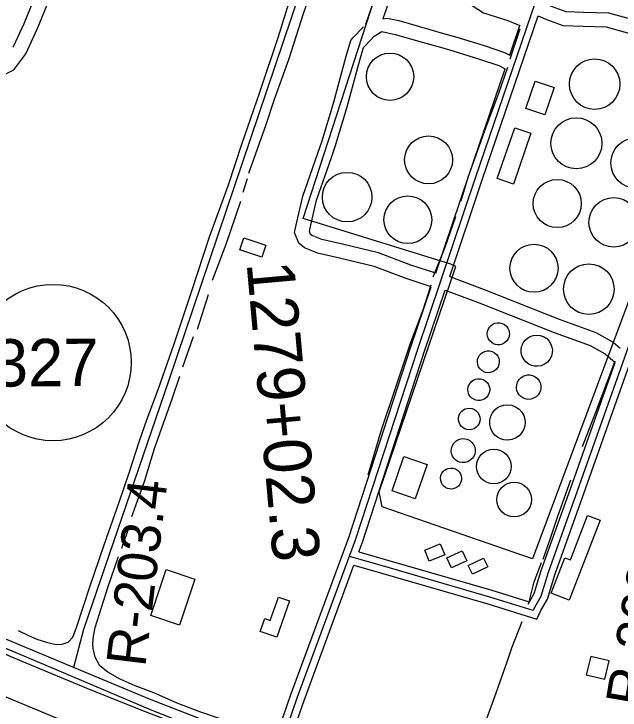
# Model space of a CAD drawing. Extents: x 3329332 to 3367211, y 631066 to 656469.
# Drawn here: x 3336928 to 3338207, y 649803 to 651272 of the extents above; entities that cross this region are included whole.
import ezdxf

# ---------------------------------------------------------------- set-up
doc = ezdxf.new("R2010")
doc.units = 0
for name, color, linetype in [('V-BLDG-OTLN', 7, 'Continuous'), ('V-DOMW-TANK', 7, 'Continuous'), ('V-LEVE-TOET', 7, 'Continuous'), ('V-RIVR-RANG-IDEN', 7, 'Continuous'), ('V-ROAD-CNTR', 7, 'Continuous'), ('V-ROAD-IDEN', 7, 'Continuous'), ('V-SITE-OTLN', 7, 'Continuous'), ('V-SURV-IDEN', 7, 'Continuous'), ('V-SURV-LINE', 7, 'Continuous'), ('V-TOPO-SHOR', 7, 'Continuous')]:
    doc.layers.add(name, color=color, linetype=linetype)

msp = doc.modelspace()

# ---------------------------------------------------------------- linework, layer by layer
at = {"layer": 'V-BLDG-OTLN'}
for points in [[(3338008.2600000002, 651072.2880000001), (3338027.802, 651129.833), (3338067.4960000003, 651116.351), (3338047.954, 651058.808)], [(3338018.4220000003, 651020.172), (3337981.5870000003, 650912.863), (3337947.645, 650924.514), (3337984.48, 651031.823)], [(3337413.113, 650799.818), (3337459.65, 650783.747), (3337450.913, 650758.446), (3337404.376, 650774.517)], [(3337799.433, 650321.372), (3337774.483, 650249.055), (3337725.877, 650265.824), (3337750.828, 650338.1410000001)], [(3338164.7060000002, 650203.573), (3338099.4760000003, 650035.297), (3338061.508, 650050.0160000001), (3338090.352, 650124.426), (3338101.8680000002, 650119.962), (3338138.252, 650213.828)], [(3337794.664, 650140.513), (3337827.538, 650154.157), (3337837.147, 650131.007), (3337804.273, 650117.363)], [(3337841.2, 650124.4450000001), (3337873.292, 650139.278), (3337883.18, 650117.885), (3337851.09, 650103.051)], [(3337886.551, 650107.985), (3337918.649, 650124.006), (3337927.759, 650105.757), (3337895.659, 650089.735)], [(3337216.929, 650002.581), (3337249.271, 650099.85), (3337309.724, 650079.7490000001), (3337277.382, 649982.479)], [(3337509.379, 650033.7390000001), (3337482.665, 649957.123), (3337447.741, 649969.301), (3337457.159, 649996.3200000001), (3337468.943, 649992.212), (3337486.237, 650041.808)], [(3338135.39169175, 649877.63821801), (3338174.2876139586, 649868.30823667), (3338183.618595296, 649907.2041588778), (3338144.7226730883, 649916.5351402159)]]:
    msp.add_lwpolyline(points, close=True, dxfattribs=at)
at = {"layer": 'V-DOMW-TANK'}
for points in [[(3337934.485, 650614.566), (3337938.015, 650617.161), (3337942.359, 650619.18), (3337947.381, 650620.313), (3337952.788, 650620.284), (3337958.161, 650618.965), (3337963.052, 650616.43), (3337967.091, 650612.946), (3337970.083, 650608.893), (3337972.012, 650604.654), (3337973.009, 650600.486), (3337973.218, 650595.97), (3337972.444, 650591.1140000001), (3337970.517, 650586.234), (3337967.4, 650581.745), (3337963.261, 650578.058), (3337958.438, 650575.486), (3337953.367, 650574.138), (3337948.454, 650573.938), (3337943.991, 650574.667), (3337939.969, 650576.1410000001), (3337935.984, 650578.552), (3337932.305, 650581.995), (3337929.315, 650586.41), (3337927.366, 650591.563), (3337926.68, 650597.054), (3337927.2800000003, 650602.43), (3337928.988, 650607.281), (3337931.501, 650611.361)], [(3338011.43, 650587.962), (3338016.74, 650591.145), (3338023.122, 650593.42), (3338030.339, 650594.354), (3338037.947, 650593.605), (3338045.343, 650591.041), (3338051.892, 650586.826), (3338057.1210000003, 650581.39), (3338060.7970000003, 650575.289), (3338062.958, 650569.0700000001), (3338063.816, 650563.071), (3338063.511, 650556.685), (3338061.786, 650549.9500000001), (3338058.432, 650543.334), (3338053.453, 650537.422), (3338047.139, 650532.779), (3338040.012, 650529.789), (3338032.696, 650528.56), (3338025.752, 650528.9230000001), (3338019.5670000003, 650530.537), (3338014.096, 650533.144), (3338008.802, 650537.059), (3338004.078, 650542.39), (3338000.447, 650549.001), (3337998.378, 650556.509), (3337998.136, 650564.333), (3337999.6890000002, 650571.818), (3338002.732, 650578.429), (3338006.806, 650583.8420000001)], [(3337913.359, 650555.1680000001), (3337916.849, 650557.759), (3337921.148, 650559.7880000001), (3337926.123, 650560.941), (3337931.488, 650560.943), (3337936.83, 650559.6630000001), (3337941.696, 650557.177), (3337945.724, 650553.74), (3337948.7120000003, 650549.737), (3337950.651, 650545.542), (3337951.665, 650541.411), (3337951.897, 650536.932), (3337951.157, 650532.109), (3337949.269, 650527.256), (3337946.205, 650522.783), (3337942.117, 650519.105), (3337937.346, 650516.524), (3337932.324, 650515.158), (3337927.448, 650514.931), (3337923.018, 650515.629), (3337919.0160000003, 650517.071), (3337915.0470000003, 650519.4400000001), (3337911.379, 650522.834), (3337908.389, 650527.2000000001), (3337906.4250000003, 650532.302), (3337905.7120000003, 650537.745), (3337906.2770000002, 650543.083), (3337907.947, 650547.91), (3337910.416, 650551.973)], [(3337894.053, 650496.99), (3337897.629, 650499.434), (3337901.989, 650501.287), (3337906.988, 650502.2390000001), (3337912.3310000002, 650502.032), (3337917.603, 650500.55), (3337922.348, 650497.881), (3337926.225, 650494.303), (3337929.0470000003, 650490.197), (3337930.815, 650485.943), (3337931.66, 650481.792), (3337931.716, 650477.321), (3337930.792, 650472.547), (3337928.724, 650467.79), (3337925.4960000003, 650463.454), (3337921.279, 650459.948), (3337916.427, 650457.566), (3337911.373, 650456.403), (3337906.507, 650456.368), (3337902.122, 650457.237), (3337898.196, 650458.83), (3337894.336, 650461.343), (3337890.815, 650464.867), (3337888.007, 650469.332), (3337886.25, 650474.4890000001), (3337885.754, 650479.939), (3337886.5270000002, 650485.231), (3337888.376, 650489.9720000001), (3337890.995, 650493.92)], [(3338006.4590000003, 650509.2930000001), (3338011.223, 650510.267), (3338016.54, 650510.29), (3338022.127, 650509.1020000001), (3338027.5640000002, 650506.5650000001), (3338032.3710000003, 650502.741), (3338036.123, 650497.916), (3338038.578, 650492.53), (3338039.715, 650487.055), (3338039.6920000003, 650481.886), (3338038.765, 650477.223), (3338036.876, 650472.574), (3338033.845, 650468.0380000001), (3338029.639, 650464.011), (3338024.414, 650460.931), (3338018.5300000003, 650459.137), (3338012.474, 650458.781), (3338006.738, 650459.774), (3338001.6920000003, 650461.855), (3337997.532, 650464.659), (3337994.161, 650468.011), (3337991.261, 650472.289), (3337989.15, 650477.4670000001), (3337988.183, 650483.306), (3337988.607, 650489.405), (3337990.465, 650495.26), (3337993.563, 650500.398), (3337997.538, 650504.498), (3338001.9620000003, 650507.4450000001)], [(3338006.376, 650410.108), (3338005.716, 650403.11), (3338003.508, 650395.747), (3337999.511, 650388.52), (3337993.7090000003, 650382.069), (3337986.393, 650377.035), (3337978.14, 650373.877), (3337969.6550000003, 650372.748), (3337961.606, 650373.488), (3337954.465, 650375.6950000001), (3337948.4050000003, 650378.946), (3337942.773, 650383.517), (3337937.772, 650389.62), (3337933.9790000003, 650397.136), (3337931.92, 650405.662), (3337931.92, 650414.554), (3337933.9790000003, 650423.08), (3337937.772, 650430.596), (3337942.773, 650436.701), (3337948.4050000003, 650441.27), (3337954.465, 650444.5210000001), (3337961.606, 650446.728), (3337969.6550000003, 650447.466), (3337978.14, 650446.339), (3337986.393, 650443.181), (3337993.7090000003, 650438.145), (3337999.511, 650431.696), (3338003.508, 650424.469), (3338005.716, 650417.106)], [(3337876.1040000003, 650436.4720000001), (3337879.909, 650438.4670000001), (3337884.415, 650439.792), (3337889.449, 650440.154), (3337894.69, 650439.335), (3337899.707, 650437.269), (3337904.078, 650434.0920000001), (3337907.484, 650430.123), (3337909.792, 650425.757), (3337911.039, 650421.362), (3337911.397, 650417.176), (3337910.937, 650412.7660000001), (3337909.478, 650408.169), (3337906.898, 650403.72), (3337903.216, 650399.823), (3337898.661, 650396.855), (3337893.609, 650395.0650000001), (3337888.4930000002, 650394.502), (3337883.698, 650395.024), (3337879.4790000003, 650396.388), (3337875.795, 650398.408), (3337872.2830000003, 650401.328), (3337869.221, 650405.203), (3337866.968, 650409.926), (3337865.829, 650415.205), (3337865.969, 650420.631), (3337867.339, 650425.755), (3337869.7060000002, 650430.211), (3337872.741, 650433.799)], [(3337869.002, 650375.063), (3337873.6920000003, 650375.919), (3337878.9080000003, 650375.833), (3337884.366, 650374.553), (3337889.648, 650371.952), (3337894.2800000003, 650368.101), (3337897.866, 650363.2930000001), (3337900.162, 650357.958), (3337901.166, 650352.5650000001), (3337901.039, 650347.4940000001), (3337900.031, 650342.938), (3337898.085, 650338.4180000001), (3337895.02, 650334.029), (3337890.809, 650330.164), (3337885.619, 650327.25), (3337879.811, 650325.612), (3337873.864, 650325.386), (3337868.256, 650326.48), (3337863.349, 650328.62), (3337859.325, 650331.459), (3337856.0870000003, 650334.819), (3337853.3310000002, 650339.0750000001), (3337851.366, 650344.1950000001), (3337850.539, 650349.944), (3337851.08, 650355.9180000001), (3337853.021, 650361.6240000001), (3337856.167, 650366.6), (3337860.15, 650370.545), (3337864.554, 650373.34)], [(3337836.611, 650309.31), (3337840.148, 650311.532), (3337844.418, 650313.16), (3337849.271, 650313.893), (3337854.414, 650313.498), (3337859.438, 650311.8740000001), (3337863.915, 650309.127), (3337867.519, 650305.533), (3337870.0870000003, 650301.476), (3337871.633, 650297.31), (3337872.299, 650293.28), (3337872.186, 650288.969), (3337871.119, 650284.4), (3337868.953, 650279.89), (3337865.682, 650275.831), (3337861.49, 650272.609), (3337856.7260000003, 650270.49), (3337851.811, 650269.556), (3337847.1210000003, 650269.699), (3337842.927, 650270.699), (3337839.199, 650272.378), (3337835.572, 650274.942), (3337832.31, 650278.469), (3337829.7660000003, 650282.876), (3337828.2630000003, 650287.912), (3337827.987, 650293.182), (3337828.9250000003, 650298.252), (3337830.884, 650302.754), (3337833.553, 650306.463)]]:
    msp.add_lwpolyline(points, close=True, dxfattribs=at)
for centre, radius in [((3337721.422526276, 651139.4142933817), 49.92223026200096), ((3338153.103905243, 651123.7239077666), 53.24630997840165), ((3338114.531359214, 650998.9432229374), 53.8207755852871), ((3337802.758725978, 650963.8763574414), 50.51238823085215), ((3338240.245628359, 650957.4500719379), 52.8947480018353), ((3337630.98572131, 650885.4010597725), 52.26802205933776), ((3338074.1135516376, 650871.9143010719), 50.777583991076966), ((3337759.032136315, 650837.666480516), 50.40586754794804), ((3338193.3709002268, 650832.2113166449), 52.236251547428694), ((3338025.1636538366, 650735.4327266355), 50.663710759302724), ((3338140.786429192, 650691.2992106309), 53.38208720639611), ((3337940.2538369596, 650317.2020386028), 36.55618293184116), ((3337983.3630298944, 650247.2283144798), 36.59716773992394)]:
    msp.add_circle(centre, radius, dxfattribs=at)
at = {"layer": 'V-LEVE-TOET'}
msp.add_lwpolyline([(3337615.179, 649642.509), (3337494.578, 649685.679), (3337361.847, 649739.015), (3337202.353, 649801.209), (3337090.813, 649845.022), (3336945.235, 649905.397), (3336818.775, 649959.046), (3336694.376, 650007.459), (3336566.857, 650058.327), (3336448.007, 650103.2270000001), (3336336.455, 650144.951), (3336224.214, 650188.074), (3336140.117, 650219.892), (3336101.211, 650237.47), (3336073.77, 650249.868), (3336031, 650261.253), (3335964.251, 650281.481), (3335912.803, 650298.14)], dxfattribs=at)
at = {"layer": 'V-ROAD-CNTR'}
for points in [[(3338668.0386264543, 654644.934683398), (3338523.253916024, 654233.618506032), (3338032.465897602, 652783.0184072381), (3337720.7975209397, 651884.8272036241), (3337530.17290219, 651315.3403425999), (3337254.259454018, 650497.35197858), (3337074.4858135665, 649973.226026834), (3337053.751855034, 649893.1841869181)], [(3337488.7839849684, 649720.3165326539), (3337488.4559856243, 649719.9745333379), (3337525.9019107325, 649828.81331566), (3337648.9226646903, 650162.451648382), (3337779.82740288, 650564.9098434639), (3337901.8621588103, 650926.380120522), (3338057.745847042, 651383.9182054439), (3338174.778612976, 651726.0105212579), (3338250.9074607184, 651927.48411831)], [(3336925.9971105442, 651201.627570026), (3336926.992108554, 651202.966567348), (3336949.9600626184, 651251.503470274), (3337022.195918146, 651429.669113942), (3337051.5438594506, 651501.026971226)], [(3336950.9020607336, 651184.842603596), (3336952.840056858, 651187.4505983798), (3336977.4420076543, 651239.4414943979), (3337049.9698625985, 651418.327136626), (3337079.289803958, 651489.616994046)], [(3337850.603261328, 651314.754343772), (3337856.251250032, 651312.717347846), (3337884.624193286, 651296.2483807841), (3337918.76212501, 651274.079425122), (3337970.20202213, 651258.3004566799), (3337995.4169717, 651247.4874783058)], [(3337670.230622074, 651249.9884733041), (3337686.025590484, 651295.213382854)], [(3338043.7518750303, 651296.33038062), (3338061.6398392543, 651288.3413965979), (3338092.073778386, 651277.0784191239), (3338129.5637034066, 651275.8814215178), (3338182.1205982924, 651274.181424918), (3338236.5274894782, 651259.1964548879), (3338315.877330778, 651231.5305102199), (3338372.983216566, 651216.867539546), (3338403.4621556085, 651217.4985382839), (3338431.4510996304, 651221.014531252), (3338448.998064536, 651207.6275580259)], [(3337715.8835307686, 651289.716393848), (3337706.3515498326, 651261.4054504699), (3337715.685531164, 651263.0954470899), (3337739.789482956, 651257.70045788), (3337805.1533522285, 651239.0574951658), (3337834.41229371, 651230.87051154)], [(3337847.313267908, 650717.9095374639), (3337916.0671304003, 650921.562130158), (3338034.0358944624, 651267.813437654)], [(3338034.0358944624, 651267.813437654), (3338050.3038619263, 651260.5474521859), (3338086.2377900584, 651247.2484787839), (3338128.599705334, 651245.8974814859), (3338177.588607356, 651244.311484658), (3338227.5955073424, 651230.538512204), (3338307.193348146, 651202.786567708), (3338369.499223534, 651186.7895997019), (3338405.648151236, 651187.536598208), (3338423.0131165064, 651189.718593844), (3338427.12110829, 651186.5846001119), (3338433.09609634, 651175.872621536), (3338433.1770961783, 651177.237618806)], [(3337643.2336760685, 651221.1075310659), (3337665.42763168, 651244.8524835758)], [(3337679.961602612, 651216.467540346), (3337688.041586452, 651225.1125230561), (3337703.960554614, 651234.9785033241), (3337732.3934977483, 651228.6145160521), (3337796.9973685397, 651210.1875529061), (3337827.765307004, 651201.5785701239)], [(3337974.0800143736, 651184.86060356), (3337995.4169717, 651247.4874783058)], [(3337569.0708243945, 650977.8390176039), (3337577.47780758, 651001.7669697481), (3337601.9867585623, 651083.9308054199), (3337628.654705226, 651182.4906083), (3337638.54268545, 651216.0885411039), (3337643.2336760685, 651221.1075310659)], [(3337834.41229371, 651230.87051154), (3337862.6042373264, 651222.9825273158), (3337919.776122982, 651204.9475633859), (3337962.8640368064, 651190.55059218), (3337974.0800143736, 651184.86060356)], [(3337597.6457672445, 650968.6650359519), (3337606.019750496, 650992.5009882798), (3337630.844700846, 651075.7248218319), (3337657.526647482, 651174.3366246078), (3337665.314631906, 651200.7965716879), (3337679.961602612, 651216.467540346)], [(3337827.765307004, 651201.5785701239), (3337854.0482544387, 651194.224584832), (3337910.510141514, 651176.4136204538), (3337951.2600600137, 651162.7986476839), (3337964.3080339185, 651156.1766609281)], [(3336816.9633286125, 651132.332708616), (3336849.357263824, 651128.1077170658), (3336886.03419047, 651132.7087078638), (3336928.043106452, 651154.0956650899), (3336950.9020607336, 651184.842603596)], [(3338448.1510662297, 651176.35062058), (3338446.835068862, 651154.1886649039), (3338432.687097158, 651116.406740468), (3338384.6771931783, 650999.6639739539), (3338299.2323640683, 650772.4064284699), (3338231.45649962, 650590.8947914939), (3338185.224592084, 650460.189052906), (3338116.4277296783, 650265.2534427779), (3338054.73185307, 650093.289786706), (3338039.5548834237, 650043.200886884), (3338026.4189096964, 650019.9609333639), (3338023.22691608, 650013.0049472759), (3337932.0060985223, 650041.746889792), (3337705.226552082, 650107.5167582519), (3337635.868690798, 650127.048719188)], [(3337645.1466722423, 650108.85275558), (3337701.1045603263, 650093.093787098), (3337927.6631072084, 650027.3889185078), (3338031.3408998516, 649994.7219838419), (3338039.7878829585, 650013.129947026), (3338053.429855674, 650037.263898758), (3338068.9778245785, 650088.578796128), (3338130.5597014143, 650260.2244528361), (3338199.367563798, 650455.1920628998), (3338245.5544714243, 650585.769801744), (3338313.2783359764, 650767.1434389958), (3338398.6371652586, 650994.1709849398), (3338446.65106923, 651110.922751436), (3338461.675039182, 651151.044671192), (3338462.542037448, 651165.648641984)], [(3337818.0013265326, 650724.8755235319), (3337887.65718722, 650931.1981108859), (3337964.3080339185, 651156.1766609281)], [(3337523.0149165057, 650823.6293260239), (3337537.211888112, 650887.157198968), (3337569.0708243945, 650977.8390176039)], [(3337552.2218580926, 650816.77133974), (3337566.103830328, 650878.885215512), (3337597.6457672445, 650968.6650359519)], [(3337554.8948527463, 650772.939427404), (3337541.0648804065, 650778.5094162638), (3337529.0809043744, 650788.500396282), (3337520.07292239, 650810.4643523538), (3337523.0149165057, 650823.6293260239)], [(3337561.831838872, 650802.4863683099), (3337556.6508492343, 650804.573364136), (3337554.0108545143, 650806.7743597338), (3337551.406859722, 650813.124347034), (3337552.2218580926, 650816.77133974)], [(3337818.0013265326, 650724.8755235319), (3337765.354431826, 650741.7304898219), (3337696.8125689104, 650767.5824381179), (3337621.461719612, 650786.0644011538), (3337577.3688077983, 650796.2293808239), (3337563.7398350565, 650801.7183698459)], [(3337808.403345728, 650696.4475803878), (3337755.4804515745, 650713.3925464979), (3337687.914586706, 650738.8764955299), (3337614.5177335, 650756.8784595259), (3337568.3408258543, 650767.523438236), (3337554.8948527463, 650772.939427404)], [(3337847.313267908, 650717.9095374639), (3337920.039122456, 650690.463592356), (3338078.270805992, 650628.035717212), (3338155.8746507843, 650599.97177334), (3338192.3105779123, 650579.7568137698), (3338207.0735483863, 650566.9398394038)], [(3337474.572013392, 649725.7305218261), (3337511.7709389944, 649833.84830559), (3337634.7486930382, 650167.3676385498), (3337765.5884313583, 650569.6288340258), (3337808.403345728, 650696.4475803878)], [(3337655.5566514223, 650137.08769911), (3337663.0966363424, 650157.5356582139), (3337794.066374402, 650560.1908529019), (3337837.710287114, 650689.467594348)], [(3337837.710287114, 650689.467594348), (3337909.2371440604, 650662.4756483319), (3338067.662827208, 650599.9697733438), (3338143.4166757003, 650572.5758281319), (3338175.0126125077, 650555.0468631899), (3338196.3215698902, 650536.545900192)], [(3337655.5566514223, 650137.08769911), (3337709.348543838, 650121.9397294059), (3337936.3490898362, 650056.1048610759), (3338015.112932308, 650031.2879107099), (3338013.049936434, 650026.7919197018), (3338025.679911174, 650049.13787501), (3338040.4858815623, 650098.0007772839), (3338102.2957579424, 650270.28243272), (3338171.08162037, 650465.1860429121), (3338196.3215698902, 650536.545900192)], [(3335451.3070599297, 650502.6739679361), (3335830.622301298, 650371.4892303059), (3336218.1535262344, 650232.9845073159), (3336467.2780279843, 650138.754695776), (3336816.516329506, 649992.2559887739), (3337213.077536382, 649826.6483199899), (3337406.717149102, 649751.5804701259), (3337593.6207752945, 649680.3776125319), (3337678.0646064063, 649661.0906511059), (3337748.784464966, 649653.3316666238), (3337841.300279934, 649661.719649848), (3337945.815070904, 649680.705611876), (3338033.0488964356, 649708.2865567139), (3338175.960610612, 649751.5904701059), (3338247.059468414, 649768.4324364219), (3338321.5703193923, 649777.4724183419), (3338384.7511930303, 649776.2554207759), (3338442.358077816, 649772.761427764), (3338528.8109049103, 649753.9364654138), (3338662.651637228, 649722.4865283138), (3338806.4693495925, 649687.4185984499), (3338886.251190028, 649663.51364626), (3338953.1790561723, 649638.9556953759), (3339090.7347810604, 649573.2078268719)], [(3337502.625957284, 649715.0425432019), (3337540.03288247, 649823.7783257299), (3337645.1466722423, 650108.85275558)]]:
    msp.add_lwpolyline(points, dxfattribs=at)
at = {"layer": 'V-ROAD-IDEN'}
msp.add_circle((3337010.55394143, 650536.4089004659), 164.99966999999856, dxfattribs=at)
at = {"layer": 'V-SITE-OTLN'}
msp.add_lwpolyline([(3338401.7830000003, 651911.888), (3338652.855, 651887.789), (3338420.387, 651191.2930000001), (3338021.826, 650122.405), (3337704.941, 650232.36), (3337698.651, 650263.66), (3337860.093, 650739.002), (3337849.867, 650744.223), (3337538.139, 650840.1900000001), (3337706.815, 651360.849), (3337932.1010000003, 652020.7490000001), (3337976.106, 652090.281), (3338174.305, 651970.534), (3338329.316, 651926.046)], close=True, dxfattribs=at)
at = {"layer": 'V-SURV-LINE'}
msp.add_lwpolyline([(3336404.936401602, 650041.5539784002), (3337707.161982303, 649500.1937651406)], dxfattribs=at)
at = {"layer": 'V-TOPO-SHOR'}
for p, q in [((3337974.9760000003, 651177.4400000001), (3337995.982, 651240.103)), ((3337423.892, 650936.159), (3337459.992, 651038.389)), ((3337411.685, 650895.75), (3337420.523, 650924.613)), ((3337315.055, 650607.169), (3337338.183, 650679.733)), ((3337284.038, 650527.215), (3337307.119, 650591.518)), ((3337155.487, 650145.054), (3337172.282, 650193.698))]:
    msp.add_line(p, q, dxfattribs=at)
for points in [[(3337459.992, 651038.389), (3337477.6410000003, 651091.983), (3337507.855, 651176.074), (3337539.393, 651275.025), (3337565.83, 651348.397), (3337594.437, 651440.3420000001), (3337630.934, 651540.0920000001), (3337664.978, 651643.985), (3337709.061, 651770.127), (3337723.326, 651809.285)], [(3336937.244, 649971.158), (3336959.073, 649960.296), (3336976.379, 649952.763), (3336999.056, 649945.613), (3337018.0330000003, 649941.7880000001), (3337029.6, 649942.136), (3337042.429, 649946.193), (3337051.991, 649957.291), (3337060.365, 649977.484), (3337088.523, 650063.236), (3337118.764, 650151.87), (3337149.84, 650242.149), (3337170.839, 650303.573), (3337192.275, 650369.125), (3337209.069, 650417.356), (3337231.711, 650477.1190000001), (3337266.9760000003, 650577.702), (3337303.117, 650687.366), (3337340.524, 650801.567), (3337380.382, 650911.211), (3337408.542, 650997.376), (3337446.7490000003, 651107.028), (3337485.825, 651224.524), (3337517.373, 651325.128)], [(3337871.6720000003, 650877.335), (3337886.225, 650927.408), (3337923.575, 651031.283), (3337951.252, 651105.058), (3337969.919, 651159.709)], [(3337347.028, 650710.2490000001), (3337375.9560000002, 650786.084), (3337406.625, 650877.191)], [(3337812.5300000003, 650717.41), (3337837.4790000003, 650779.817), (3337859.923, 650844.7710000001)], [(3337675.335, 650299.553), (3337703.544, 650394.39), (3337731.2800000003, 650478.493), (3337763.628, 650574.96), (3337791.301, 650647.909), (3337808.301, 650700.086)], [(3338127.306, 650359.5920000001), (3338155.515, 650431.54), (3338179.2060000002, 650495.184), (3338196.063, 650539.701)], [(3337176.5160000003, 650211.8470000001), (3337203.367, 650285.629), (3337224.826, 650355.312), (3337262.179, 650460.012), (3337278.146, 650507.834)], [(3338044.593, 650121.737), (3338059.116, 650164.149), (3338074.543, 650210.338), (3338102.949, 650288.688)], [(3337558.8986264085, 649668.7355608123), (3337219.44597904, 649802.1964085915), (3336949.446621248, 649916.8564216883), (3336655.767294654, 650039.3600562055), (3336283.1626909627, 650183.8019739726), (3336155.2848952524, 650229.3128707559)], [(3337454.757, 649747.256), (3337408.196, 649767.345), (3337364.1, 649784.942), (3337320.4020000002, 649799.644), (3337272.593, 649818.089), (3337223.151, 649839.846), (3337183.9930000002, 649854.113), (3337151.86, 649868.75), (3337126.329, 649882.936), (3337109.47, 649896.25), (3337099.664, 649914.8910000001), (3337095.222, 649933.0920000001), (3337094.458, 649943.834), (3337095.784, 649959.11), (3337099.603, 649977.261), (3337126.1040000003, 650062.198), (3337148.778, 650127.33)], [(3338015.602, 650034.751), (3338025.551, 650073.73), (3338040.833, 650114.326)], [(3337895.417, 649685.976), (3337906.943, 649730.2440000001), (3337920.792, 649772.164), (3337942.115, 649829.598), (3337968.598, 649905.278), (3337978.486, 649934.388), (3338000.068, 649990.231)]]:
    msp.add_lwpolyline(points, dxfattribs=at)

# ---------------------------------------------------------------- texts
at = {"layer": 'V-RIVR-RANG-IDEN'}
for s, height, rotation, p in [('R-203.4', 82.99999799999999, 83.16435010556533, (3337205.021892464, 649892.6906353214)), ('R-203.25', 82.99999800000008, 80.4516786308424, (3338257.8058101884, 649806.8488794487))]:
    msp.add_text(s, height=height, rotation=rotation, dxfattribs=at).set_placement(p)
at = {"layer": 'V-ROAD-IDEN'}
msp.add_text('327', height=100.000131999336, rotation=0.39154994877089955, dxfattribs=at).set_placement((3336883.7341950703, 650485.5410022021))
at = {"layer": 'V-SURV-IDEN'}
msp.add_text('1279+02.3', height=100.00000000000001, rotation=275.1145987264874, dxfattribs=at).set_placement((3337418.756815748, 650746.1842073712))

doc.saveas('drawing.dxf')
